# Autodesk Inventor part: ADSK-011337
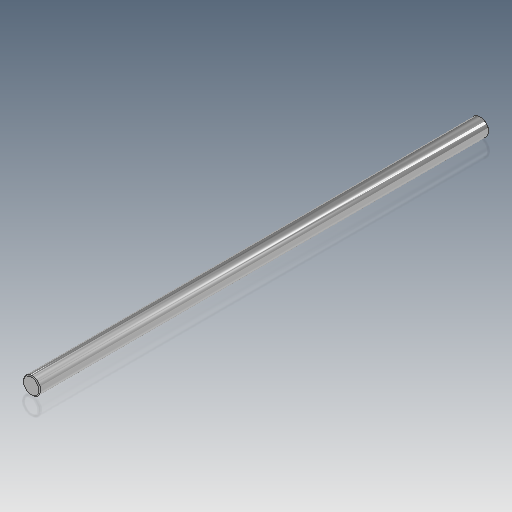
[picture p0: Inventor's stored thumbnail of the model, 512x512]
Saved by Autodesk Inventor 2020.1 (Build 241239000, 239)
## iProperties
Created: 1999-12
Part Number: ADSK-011337
Material: Acier doux
Description: SHFT-T,TH,AX,07-06,188,ADJUST,WIDTH,LH
Document SubType Name: Modeling
Designer: sspink
Density: 7.86 g/cm^3
Appearance: Chrom - poliert
Mass: 1283.55 g
Surface Area: 332.247 cm^2
Volume: 163.302 cm^3
Control State: 0
Master: False
Checked Out: False
Shininess: 0.0
Length Units: 11269
Angle Units: 11279
Time Units: 11290
Mass Units: 11283
Length Display Precision: 3
Angle Display Precision: 2
Compacted: True
Cutlength: 18.81
Material Desc: THREADED-ROD,0.750-06LH ACME
Material_number: A084662
Dimensions: 20x20x520 mm
Mass: 1,284 kg
DocNumber: ADSK-011337.ipt
Folder: 01 - Themengebiete\Simplification\01 - Packaging machine\
VDS_Category: 3D Komponenten
Density: 0.0
Volumn: 0.0
Area: 0.0
PropertySet Name: Model Information
Author: sspink
Revision Number: -
Title: shaft
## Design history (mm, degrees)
node "Solide1"
  node "Extrusion1" dims "d1" = 520, "d2" = 0
sketch "Sketch1"
  geometry: C1 r 10 at (0, 0); 1 further point
  constraints: 1 centre point, 1 coincident
  dimensions: "d0" = 20 diameter of C1
chamfer "Fase1" distance "d3" = 1; stored, may be unused: second distance "d4" = 2, angle "d5" = 45 deg
node "Corps solides"
node "Corps surfaciques"
